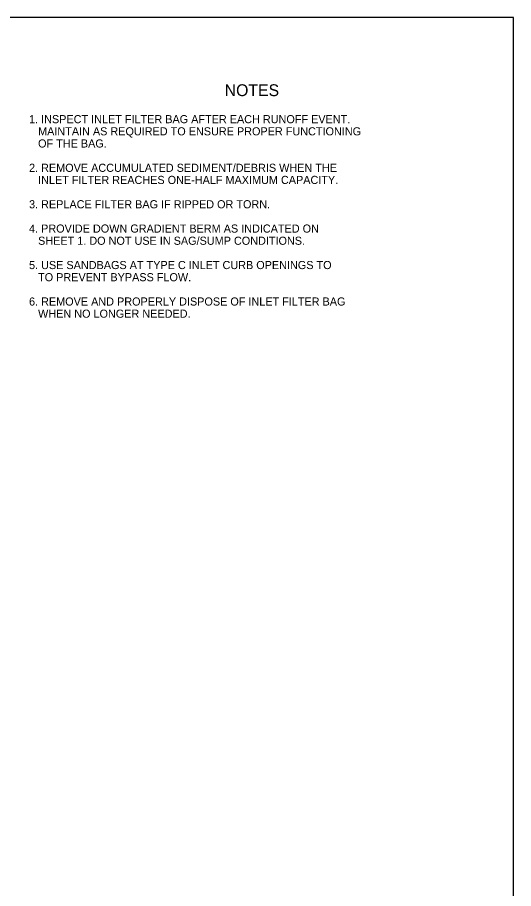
# Model space of a CAD drawing. Extents: x 636183 to 639890, y 299162 to 300538.
# Drawn here: x 637104.5 to 637287.9, y 299607.2 to 299929.4 of the extents above; entities that cross this region are included whole.
import ezdxf

# ---------------------------------------------------------------- set-up
doc = ezdxf.new("R2010")
doc.units = 0
doc.layers.add('1', color=7, linetype='Continuous')
doc.layers.add('Default', color=7, linetype='Continuous')

msp = doc.modelspace()

# ---------------------------------------------------------------- linework, layer by layer
at = {"layer": '1'}
msp.add_lwpolyline([(637287.91, 299365.45), (637287.91, 299929.45), (636501.91, 299929.45), (636501.91, 299365.45), (637287.91, 299365.45), (637287.91, 299391.81), (637087.91, 299391.81), (637087.91, 299456.49), (637287.91, 299456.49), (637287.91, 299485.45), (637087.91, 299485.45), (637087.91, 299365.45), (637166.72, 299365.45), (637166.72, 299391.81), (637166.72, 299365.45), (637243.72, 299365.45), (637243.72, 299391.81), (637243.72, 299379.49), (637287.91, 299379.49)], dxfattribs=at)

# ---------------------------------------------------------------- texts
at = {"layer": 'Default'}
for s, height, p in [('NOTES', 4.372, (637181.12, 299900.34)), ('1. INSPECT INLET FILTER BAG AFTER EACH RUNOFF EVENT.', 2.998, (637108.82, 299890.32)), ('   MAINTAIN AS REQUIRED TO ENSURE PROPER FUNCTIONING', 2.998, (637108.82, 299885.82)), ('   OF THE BAG.', 2.998, (637108.82, 299881.33)), ('2. REMOVE ACCUMULATED SEDIMENT/DEBRIS WHEN THE', 2.998, (637108.82, 299872.33)), ('   INLET FILTER REACHES ONE-HALF MAXIMUM CAPACITY.', 2.998, (637108.82, 299867.84)), ('3. REPLACE FILTER BAG IF RIPPED OR TORN.', 2.998, (637108.82, 299858.84)), ('4. PROVIDE DOWN GRADIENT BERM AS INDICATED ON', 2.998, (637108.82, 299849.85)), ('   SHEET 1. DO NOT USE IN SAG/SUMP CONDITIONS.', 2.998, (637108.82, 299845.35)), ('5. USE SANDBAGS AT TYPE C INLET CURB OPENINGS TO', 2.998, (637108.82, 299836.36)), ('   TO PREVENT BYPASS FLOW.', 2.998, (637108.82, 299831.86)), ('6. REMOVE AND PROPERLY DISPOSE OF INLET FILTER BAG', 2.998, (637108.82, 299822.87)), ('   WHEN NO LONGER NEEDED.', 2.998, (637108.82, 299818.37))]:
    msp.add_text(s, height=height, dxfattribs=at).set_placement(p)

doc.saveas('drawing.dxf')
